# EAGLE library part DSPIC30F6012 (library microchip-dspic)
dsPIC General DSP with CAN and I2S ports
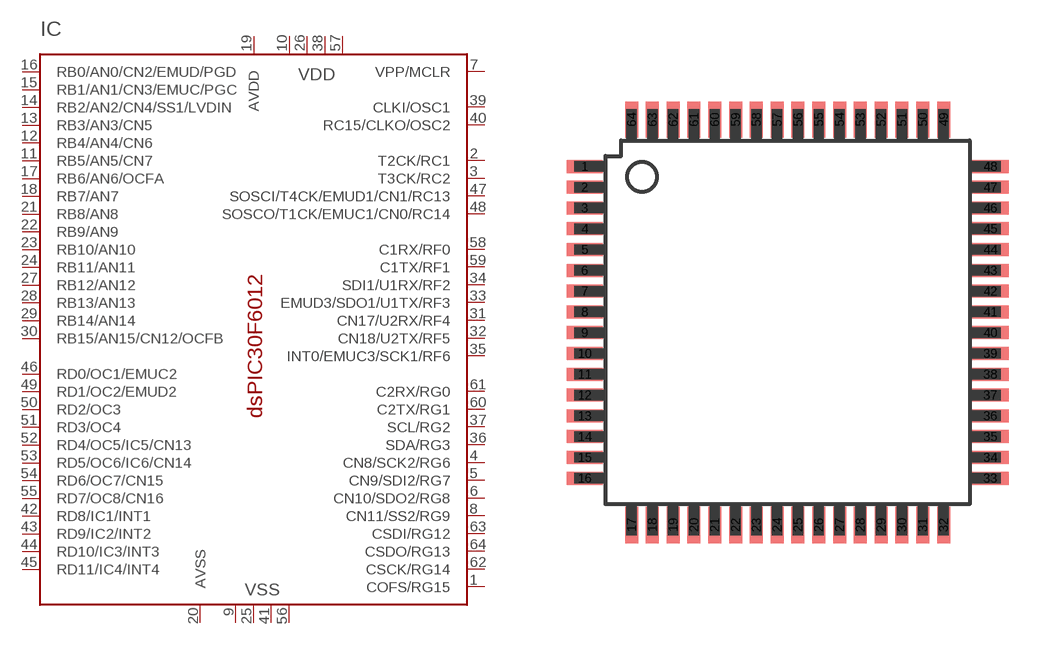
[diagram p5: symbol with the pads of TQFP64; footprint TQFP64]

Designator prefix IC

## DSPIC30F6012/PF  [TQFP64]
1  COFS/RG15
2  T2CK/RC1
3  T3CK/RC2
4  CN8/SCK2/RG6
5  CN9/SDI2/RG7
6  CN10/SDO2/RG8
7  VPP/MCLR  in
8  CN11/SS2/RG9
9  VSS  pwr
10  VDD  pwr
11  RB5/AN5/CN7
12  RB4/AN4/CN6
13  RB3/AN3/CN5
14  RB2/AN2/CN4/SS1/LVDIN
15  RB1/AN1/CN3/EMUC/PGC
16  RB0/AN0/CN2/EMUD/PGD
17  RB6/AN6/OCFA
18  RB7/AN7
19  AVDD  pwr
20  AVSS  pwr
21  RB8/AN8
22  RB9/AN9
23  RB10/AN10
24  RB11/AN11
25  VSS  pwr
26  VDD  pwr
27  RB12/AN12
28  RB13/AN13
29  RB14/AN14
30  RB15/AN15/CN12/OCFB
31  CN17/U2RX/RF4
32  CN18/U2TX/RF5
33  EMUD3/SDO1/U1TX/RF3
34  SDI1/U1RX/RF2
35  INT0/EMUC3/SCK1/RF6
36  SDA/RG3
37  SCL/RG2
38  VDD  pwr
39  CLKI/OSC1  in
40  RC15/CLKO/OSC2
41  VSS  pwr
42  RD8/IC1/INT1
43  RD9/IC2/INT2
44  RD10/IC3/INT3
45  RD11/IC4/INT4
46  RD0/OC1/EMUC2
47  SOSCI/T4CK/EMUD1/CN1/RC13
48  SOSCO/T1CK/EMUC1/CN0/RC14
49  RD1/OC2/EMUD2
50  RD2/OC3
51  RD3/OC4
52  RD4/OC5/IC5/CN13
53  RD5/OC6/IC6/CN14
54  RD6/OC7/CN15
55  RD7/OC8/CN16
56  VSS  pwr
57  VDD  pwr
58  C1RX/RF0
59  C1TX/RF1
60  C2TX/RG1
61  C2RX/RG0
62  CSCK/RG14
63  CSDI/RG12
64  CSDO/RG13

## Footprint TQFP64 (pad centres in mm)
Thin Quad Flat Pack
smd 1.4 x 0.5: 1 -7.8,6; 2 -7.8,5.2; 3 -7.8,4.4; 4 -7.8,3.6; 5 -7.8,2.8; 6 -7.8,2; 7 -7.8,1.2; 8 -7.8,0.4; 9 -7.8,-0.4; 10 -7.8,-1.2; 11 -7.8,-2; 12 -7.8,-2.8; 13 -7.8,-3.6; 14 -7.8,-4.4; 15 -7.8,-5.2; 16 -7.8,-6; 33 7.8,-6; 34 7.8,-5.2; 35 7.8,-4.4; 36 7.8,-3.6; 37 7.8,-2.8; 38 7.8,-2; 39 7.8,-1.2; 40 7.8,-0.4; 41 7.8,0.4; 42 7.8,1.2; 43 7.8,2; 44 7.8,2.8; 45 7.8,3.6; 46 7.8,4.4; 47 7.8,5.2; 48 7.8,6
smd 0.5 x 1.4: 17 -6,-7.8; 18 -5.2,-7.8; 19 -4.4,-7.8; 20 -3.6,-7.8; 21 -2.8,-7.8; 22 -2,-7.8; 23 -1.2,-7.8; 24 -0.4,-7.8; 25 0.4,-7.8; 26 1.2,-7.8; 27 2,-7.8; 28 2.8,-7.8; 29 3.6,-7.8; 30 4.4,-7.8; 31 5.2,-7.8; 32 6,-7.8; 49 6,7.8; 50 5.2,7.8; 51 4.4,7.8; 52 3.6,7.8; 53 2.8,7.8; 54 2,7.8; 55 1.2,7.8; 56 0.4,7.8; 57 -0.4,7.8; 58 -1.2,7.8; 59 -2,7.8; 60 -2.8,7.8; 61 -3.6,7.8; 62 -4.4,7.8; 63 -5.2,7.8; 64 -6,7.8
